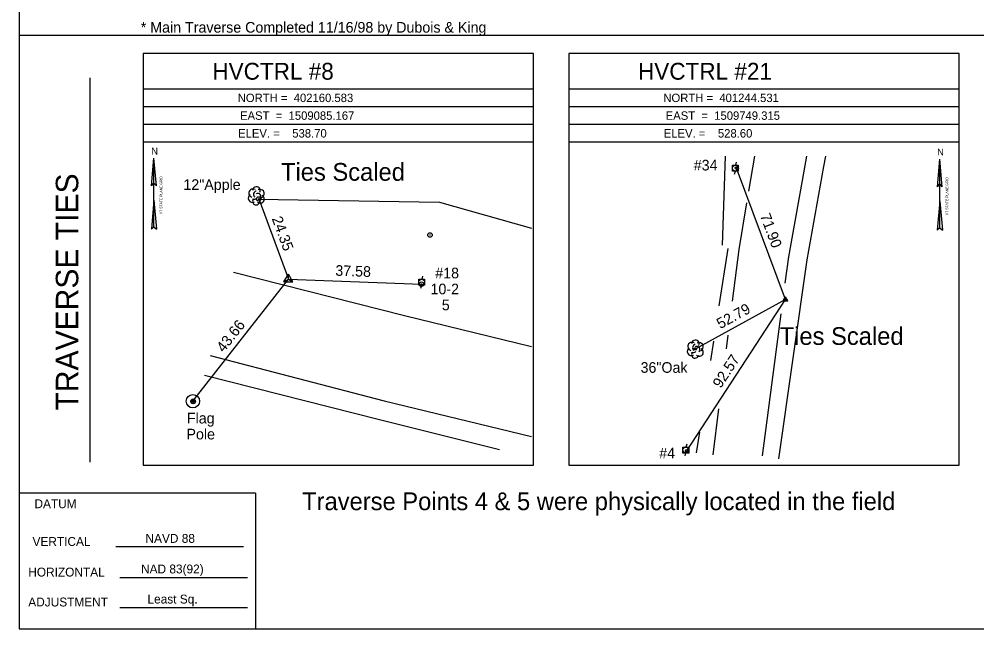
# Model space of a CAD drawing. Extents: x 1508412 to 1509054, y 401108 to 401963.
# Drawn here: x 1508413.7 to 1508683.7, y 401543.2 to 401715.1 of the extents above; entities that cross this region are included whole.
import ezdxf

# ---------------------------------------------------------------- set-up
doc = ezdxf.new("R2010")
doc.units = 0
for name, color, linetype in [('CBP', 7, 'Continuous'), ('CPSM', 7, 'Continuous'), ('Default', 7, 'Continuous'), ('LAWA', 7, 'Continuous'), ('Level 12', 7, 'Continuous'), ('Level 3', 7, 'Continuous'), ('Level 5', 7, 'Continuous'), ('LFNC', 7, 'Continuous'), ('LFP', 7, 'Continuous'), ('LTD', 7, 'Continuous'), ('LWS', 7, 'Continuous'), ('NBL2', 7, 'Continuous'), ('NNA_P', 7, 'Continuous'), ('PET', 7, 'Continuous'), ('UP', 7, 'Continuous'), ('UPGW', 7, 'Continuous')]:
    doc.layers.add(name, color=color, linetype=linetype)

msp = doc.modelspace()

# ---------------------------------------------------------------- linework, layer by layer
at = {"layer": 'CBP'}
for centre, radius in [((1508615.89, 401673.07), 0.344), ((1508615.89, 401673.07), 0.0458), ((1508481.23, 401664.39), 0.625), ((1508481.23, 401664.39), 0.0833), ((1508527.13, 401640.37), 0.625), ((1508527.13, 401640.37), 0.0833), ((1508604.3, 401622.07), 0.344), ((1508604.3, 401622.07), 0.0458), ((1508462.68, 401607.36), 0.625), ((1508462.68, 401607.36), 0.0833), ((1508601.91, 401593.39), 0.344), ((1508601.91, 401593.39), 0.344), ((1508601.91, 401593.39), 0.0458), ((1508601.91, 401593.39), 0.0458)]:
    msp.add_circle(centre, radius, dxfattribs=at)
at = {"layer": 'CPSM'}
for p, q in [((1508488.34, 401641.01), (1508489.59, 401643.17)), ((1508488.34, 401641.01), (1508489.59, 401641.73)), ((1508488.34, 401641.01), (1508490.84, 401641.01)), ((1508490.84, 401641.01), (1508489.59, 401643.17)), ((1508489.59, 401641.73), (1508489.59, 401643.17)), ((1508489.59, 401641.73), (1508489.59, 401641.73)), ((1508489.59, 401641.73), (1508490.84, 401641.01)), ((1508629.06, 401635.64), (1508629.75, 401636.83)), ((1508629.06, 401635.64), (1508629.75, 401636.04)), ((1508629.06, 401635.64), (1508630.44, 401635.64)), ((1508630.44, 401635.64), (1508629.75, 401636.83)), ((1508629.75, 401636.04), (1508629.75, 401636.83)), ((1508629.75, 401636.04), (1508629.75, 401636.04)), ((1508629.75, 401636.04), (1508630.44, 401635.64))]:
    msp.add_line(p, q, dxfattribs=at)
at = {"layer": 'Default'}
for p, q in [((1508629.75, 401636.04), (1508615.89, 401673.07)), ((1508481.23, 401664.39), (1508489.59, 401641.73)), ((1508462.68, 401607.36), (1508489.59, 401641.73)), ((1508489.59, 401641.73), (1508527.13, 401640.37)), ((1508601.91, 401593.39), (1508629.75, 401636.04)), ((1508629.75, 401636.04), (1508604.3, 401622.07))]:
    msp.add_line(p, q, dxfattribs=at)
at = {"layer": 'LAWA'}
for p, q in [((1508613.47, 401650.44), (1508610.96, 401634.25)), ((1508609.43, 401624.33), (1508608.58, 401618.84)), ((1508605.46, 401598.68), (1508604.55, 401592.79))]:
    msp.add_line(p, q, dxfattribs=at)
for points in [[(1508612.78, 401676.43), (1508611.94, 401651.34)], [(1508481, 401664.29), (1508532.21, 401663.48), (1508558.12, 401656.19)]]:
    msp.add_lwpolyline(points, dxfattribs=at)
at = {"layer": 'Level 12'}
for radius in [1.87, 0.25]:
    msp.add_circle((1508462.68, 401607.36), radius, dxfattribs=at)
at = {"layer": 'LFNC'}
msp.add_line((1508635.72, 401647.19), (1508627.79, 401591.14), dxfattribs=at)
msp.add_lwpolyline([(1508640.98, 401676.43), (1508640.43, 401673.55), (1508635.72, 401647.19)], dxfattribs=at)
at = {"layer": 'LFP'}
for radius in [0.625, 0.0833]:
    msp.add_circle((1508462.75, 401607.3), radius, dxfattribs=at)
at = {"layer": 'LTD'}
for p, q in [((1508480.53, 401665.31), (1508480.53, 401665.31)), ((1508480.53, 401665.31), (1508480.53, 401665.31)), ((1508604.3, 401622.1), (1508604.3, 401622.1)), ((1508604.3, 401622.1), (1508604.3, 401622.1))]:
    msp.add_line(p, q, dxfattribs=at)
for centre in [(1508480.57, 401666.74), (1508604.34, 401623.54)]:
    msp.add_arc(centre, 1.05, 335.5272, 180.9563, dxfattribs=at)
for centre, major_axis, ratio, start_param, end_param in [((1508479.44, 401664.6), (0.58, -1.04), 0.959034, 3.141593, 6.283185), ((1508479.74, 401665.97), (1.21, -0.51), 0.895232, 1.570796, 4.712389), ((1508480.32, 401665.77), (-0.208, -0.792), 0.645439, 3.141593, 6.283185), ((1508481.03, 401665.14), (-0.5, 0.667), 0.989748, 3.141593, 6.283185), ((1508481.53, 401664.47), (-1.09, 0.79), 0.841452, 1.570796, 4.712389), ((1508481.57, 401665.89), (-1.14, -0.48), 0.949671, 1.570796, 4.712389), ((1508480.53, 401663.81), (0.26, 1.06), 0.942809, 1.570796, 4.712389), ((1508480.07, 401664.56), (-0.625, -0.083), 0.423636, 0, 3.141593), ((1508603.21, 401621.4), (0.58, -1.04), 0.959034, 3.141593, 6.283185), ((1508603.5, 401622.77), (1.21, -0.51), 0.895232, 1.570796, 4.712389), ((1508604.09, 401622.56), (-0.208, -0.792), 0.645439, 3.141593, 6.283185), ((1508604.8, 401621.94), (-0.5, 0.667), 0.989748, 3.141593, 6.283185), ((1508605.3, 401621.27), (-1.09, 0.79), 0.841452, 1.570796, 4.712389), ((1508605.34, 401622.69), (-1.14, -0.48), 0.949671, 1.570796, 4.712389), ((1508604.3, 401620.6), (0.26, 1.06), 0.942809, 1.570796, 4.712389), ((1508603.84, 401621.35), (-0.625, -0.083), 0.423636, 0, 3.141593)]:
    msp.add_ellipse(centre, major_axis=major_axis, ratio=ratio, start_param=start_param, end_param=end_param, dxfattribs=at)
at = {"layer": 'LWS'}
msp.add_lwpolyline([(1508465.97, 401614.7), (1508515.25, 401602.19), (1508549.15, 401593.74)], dxfattribs=at)
at = {"layer": 'NBL2'}
for p, q in [((1508413.7, 401710.54), (1509053.7, 401710.54)), ((1508433.7, 401590.21), (1508433.7, 401698.54)), ((1508558.69, 401695.37), (1508448.69, 401695.37)), ((1508678.69, 401695.37), (1508568.69, 401695.37)), ((1508558.69, 401690.37), (1508448.69, 401690.37)), ((1508678.69, 401690.37), (1508568.69, 401690.37)), ((1508558.69, 401685.37), (1508448.69, 401685.37)), ((1508678.69, 401685.37), (1508568.69, 401685.37)), ((1508558.69, 401680.37), (1508448.69, 401680.37)), ((1508678.69, 401680.37), (1508568.69, 401680.37)), ((1508480.36, 401581.46), (1508413.7, 401581.46)), ((1508480.36, 401581.46), (1508480.36, 401543.21)), ((1508480.36, 401581.46), (1508480.36, 401543.21)), ((1508440.94, 401566.44), (1508476.94, 401566.4)), ((1508442.05, 401557.66), (1508478.05, 401557.66)), ((1508442.05, 401549.23), (1508478.05, 401549.19))]:
    msp.add_line(p, q, dxfattribs=at)
for points in [[(1508413.7, 401543.21), (1509053.7, 401543.21), (1509053.7, 401963.21), (1508413.7, 401963.21)], [(1508448.69, 401589.37), (1508558.69, 401589.37), (1508558.69, 401705.37), (1508448.69, 401705.37)], [(1508568.69, 401589.37), (1508678.69, 401589.37), (1508678.69, 401705.37), (1508568.69, 401705.37)]]:
    msp.add_lwpolyline(points, close=True, dxfattribs=at)
at = {"layer": 'NNA_P'}
for p, q in [((1508450.99, 401668.11), (1508451.69, 401675.9)), ((1508451.69, 401656.52), (1508451.69, 401675.9)), ((1508452.38, 401668.11), (1508451.69, 401675.9)), ((1508672.57, 401667.83), (1508673.26, 401675.62)), ((1508673.27, 401656.25), (1508673.26, 401675.62)), ((1508673.96, 401667.83), (1508673.26, 401675.62)), ((1508450.99, 401668.11), (1508451.69, 401668.87)), ((1508452.38, 401668.11), (1508451.69, 401668.87)), ((1508672.57, 401667.83), (1508673.27, 401668.6)), ((1508673.96, 401667.83), (1508673.27, 401668.6)), ((1508451.69, 401664.05), (1508450.97, 401655.88)), ((1508451.69, 401664.05), (1508452.41, 401655.88)), ((1508673.27, 401663.77), (1508672.55, 401655.61)), ((1508673.27, 401663.77), (1508673.99, 401655.61)), ((1508451.69, 401656.52), (1508450.97, 401655.88)), ((1508451.69, 401656.52), (1508452.41, 401655.88)), ((1508673.27, 401656.25), (1508672.55, 401655.61)), ((1508673.27, 401656.25), (1508673.99, 401655.61))]:
    msp.add_line(p, q, dxfattribs=at)
at = {"layer": 'PET'}
for p, q in [((1508616.57, 401650.11), (1508614.74, 401635.61)), ((1508630.59, 401648.1), (1508629.59, 401640.63)), ((1508628.44, 401631.97), (1508623.13, 401591.99)), ((1508613.53, 401626.03), (1508613.04, 401622.16)), ((1508610.9, 401605.25), (1508609.26, 401592.23))]:
    msp.add_line(p, q, dxfattribs=at)
for points in [[(1508621, 401676.43), (1508619.34, 401666.57)], [(1508635.63, 401676.43), (1508635.38, 401674.81), (1508630.59, 401648.1)], [(1508618.78, 401663.27), (1508616.57, 401650.11)], [(1508474.16, 401643.75), (1508522.37, 401631.49), (1508558.12, 401622.8)], [(1508467.59, 401620.24), (1508516.61, 401607.48), (1508558.12, 401597.47)]]:
    msp.add_lwpolyline(points, dxfattribs=at)
at = {"layer": 'UP'}
for p, q in [((1508614.78, 401672.22), (1508614.78, 401673.89)), ((1508614.78, 401673.89), (1508616.45, 401673.89)), ((1508615.87, 401674.72), (1508615.62, 401673.89)), ((1508615.62, 401673.05), (1508615.62, 401673.05)), ((1508616.45, 401673.89), (1508616.45, 401672.22)), ((1508616.45, 401672.22), (1508614.78, 401672.22)), ((1508615.37, 401671.39), (1508615.62, 401672.22)), ((1508526.34, 401640.1), (1508526.34, 401641.77)), ((1508526.34, 401641.77), (1508528.01, 401641.77)), ((1508527.43, 401642.6), (1508527.18, 401641.77)), ((1508527.18, 401640.94), (1508527.18, 401640.94)), ((1508528.01, 401641.77), (1508528.01, 401640.1)), ((1508528.01, 401640.1), (1508526.34, 401640.1)), ((1508526.93, 401639.27), (1508527.18, 401640.1)), ((1508601.93, 401595.26), (1508601.68, 401594.43)), ((1508600.84, 401592.76), (1508600.84, 401594.43)), ((1508600.84, 401594.43), (1508602.51, 401594.43)), ((1508602.51, 401592.76), (1508600.84, 401592.76)), ((1508601.43, 401591.93), (1508601.68, 401592.76)), ((1508601.68, 401593.6), (1508601.68, 401593.6)), ((1508602.51, 401594.43), (1508602.51, 401592.76))]:
    msp.add_line(p, q, dxfattribs=at)
for centre in [(1508615.62, 401673.05), (1508527.18, 401640.94), (1508601.68, 401593.6)]:
    msp.add_circle(centre, 0.833, dxfattribs=at)
at = {"layer": 'UPGW'}
for radius in [0.625, 0.0833]:
    msp.add_circle((1508529.52, 401654.23), radius, dxfattribs=at)

# ---------------------------------------------------------------- texts
at = {"layer": 'Level 3'}
for s, p in [('* Main Traverse Completed 11/16/98 by Dubois & King', (1508447.98, 401711.26)), ('#34', (1508603.88, 401672.41)), ('12"Apple', (1508460, 401666.93)), ('#18', (1508531.02, 401642)), ('10-2', (1508529.67, 401637.5)), ('5', (1508532.86, 401633)), ('36"Oak', (1508588.89, 401615.38)), ('Flag', (1508460.99, 401601.1)), ('Pole', (1508460.87, 401596.6)), ('#4', (1508594.16, 401591.24))]:
    msp.add_text(s, height=3, dxfattribs=at).set_placement(p)
for s, rotation, p in [('24.35', 290.2582, (1508484.87, 401658.85)), ('71.90', 290.5229, (1508622.51, 401659.67)), ('37.58', 357.9355, (1508502.79, 401642.75)), ('52.79', 28.754, (1508611.37, 401627.66)), ('43.66', 51.9289, (1508471.39, 401620.92)), ('92.57', 56.8626, (1508611.5, 401610.83))]:
    msp.add_text(s, height=3, rotation=rotation, dxfattribs=at).set_placement(p)
at = {"layer": 'Level 5'}
for s, p in [('Ties Scaled', (1508487.52, 401669.51)), ('Ties Scaled', (1508628.1, 401623.24)), ('Traverse Points 4 & 5 were physically located in the field', (1508493.48, 401576.66))]:
    msp.add_text(s, height=5, dxfattribs=at).set_placement(p)
at = {"layer": 'NBL2'}
for s, height, p in [('     HVCTRL #8     ', 4.75, (1508459.34, 401698)), ('     HVCTRL #21    ', 4.75, (1508579.34, 401698)), ('NORTH =  402160.583 ', 2.375, (1508475.31, 401691.69)), ('NORTH =  401244.531 ', 2.375, (1508595.31, 401691.69)), ('EAST  =  1509085.167', 2.375, (1508475.97, 401686.69)), ('EAST  =  1509749.315', 2.375, (1508595.97, 401686.69)), ('ELEV. =    538.70   ', 2.375, (1508475.42, 401681.69)), ('ELEV. =    528.60   ', 2.375, (1508595.42, 401681.69)), ('DATUM', 2.5, (1508418.01, 401577.22)), ('  NAVD 88 ', 2.5, (1508447.46, 401567.45)), ('HORIZONTAL', 2.5, (1508416.27, 401557.96)), ('NAD 83(92) ', 2.5, (1508448.06, 401558.83)), ('ADJUSTMENT', 2.5, (1508416.27, 401549.52)), (' Least Sq.', 2.5, (1508448.95, 401550.35))]:
    msp.add_text(s, height=height, dxfattribs=at).set_placement(p)
for s, height, rotation, p in [('TRAVERSE TIES', 6.3332, 90, (1508430.36, 401604.75)), ('VERTICAL', 2.5, 0.1439, (1508417.47, 401566.55))]:
    msp.add_text(s, height=height, rotation=rotation, dxfattribs=at).set_placement(p)
at = {"layer": 'NNA_P'}
for p in [(1508450.93, 401676.91), (1508672.5, 401676.63)]:
    msp.add_text('N', height=1.97, dxfattribs=at).set_placement(p)
for p in [(1508454.04, 401660.09), (1508675.62, 401659.81)]:
    msp.add_text('VT STATE PLANE GRID', height=0.7, rotation=90.0204, dxfattribs=at).set_placement(p)

doc.saveas('drawing.dxf')
